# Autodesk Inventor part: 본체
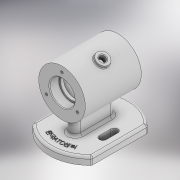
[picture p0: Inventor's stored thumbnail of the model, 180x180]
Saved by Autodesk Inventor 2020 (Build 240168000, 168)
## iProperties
Created: 2022-02
Part Number: 본체
Material: 일반
Document SubType Name: Modeling
Designer: 602-01
Density: 1 g/cm^3
Appearance: 기본값
Author: 602-01
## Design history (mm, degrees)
sketch "스케치1"
  geometry: L1 (0, 52)-(0, -52); L2 (-38, 35.496)-(-38, -35.496); L3 (38, -35.496)-(38, 35.496); A1 r 52 centre (0, 0) between (-38, -35.496) and (38, -35.496); A2 r 52 centre (0, 0) between (38, 35.496) and (-38, 35.496); 3 further points
  constraints: 6 end point, 6 point on circle, 3 coincident, 2 centre point, 2 midpoint, 1 horizontal alignment, 1 parallel, 1 vertical
  dimensions: "d1" = 76 distance between parallel lines of L2 L3; "d3" = 38 distance between parallel lines of L1 L3; "d4" = 52 radius of A1
extrude "돌출1" new body sketch "스케치1" distance "d5" = 10; taper "d6" = 0 deg
sketch "스케치2"
  geometry: 1 further point
sketch "스케치3"
  geometry: L1 (62, 36)-(62, -36); L2 (0, 35.496)-(0, -35.496) reference; L3 (62, 36)-(92, 36); L4 (62, -36)-(92, -36); L5 (92, -36)-(92, 36); L6 (78, 36)-(78, 24); L7 (78, 24)-(76, 24); L8 (76, 24)-(76, 20); L9 (76, 20)-(87, 20); L10 (87, 20)-(87, -20); L11 (87, -20)-(76, -20); L12 (76, -20)-(76, -24); L13 (76, -24)-(78, -24); L14 (78, -24)-(78, -36); 5 further points
  constraints: 26 end point, 10 perpendicular, 4 midpoint, 2 horizontal, 2 horizontal alignment, 2 point on line, 1 vertical
  dimensions: "d7" = 62 distance between parallel lines of L2 L1; "d8" = 72 distance of L1.start L1.end; "d9" = 60 diameter of L5 L1; "d10" = 32 diameter of L14 L1; "d11" = 28 diameter of L12 L1; "d12" = 50 diameter of L10 L1; "d13" = 28 diameter of L8 L1; "d14" = 32 diameter of L6 L1; "d15" = 12 distance of L6.start L6.end; "d16" = 12 distance of L13.end L14.end; "d17" = 40 distance of L9.end L10.end
revolve "회전1" sketch "스케치3" stored, may be unused: angle "d18" = 90 deg
sketch "스케치5"
  geometry: L1 (0, -19)-(0, 19); L2 (-7, -19)-(-7, 19); L3 (7, 19)-(7, -19); A1 r 7 centre (0, -19) between (-7, -19) and (7, -19); A2 r 7 centre (0, 19) between (7, 19) and (-7, 19); 1 further point
  constraints: 8 end point, 4 point on circle, 4 tangent, 2 centre point, 1 midpoint, 1 parallel, 1 vertical
  dimensions: "d21" = 14 distance between parallel lines of L3 L2; "d22" = 38 distance of L3.start L3.end
extrude "돌출2" join sketch "스케치5" stored distance "d23" = 10; taper "d24" = 0 deg
sketch "스케치6"
  geometry: L1 (-24, -7.5)-(-24, 7.5); L2 (-28.5, -7.5)-(-28.5, 7.5); L3 (-19.5, 7.5)-(-19.5, -7.5); L4 (24, -7.5)-(24, 7.5); L5 (19.5, -7.5)-(19.5, 7.5); L6 (28.5, 7.5)-(28.5, -7.5); A1 r 4.5 centre (-24, -7.5) between (-28.5, -7.5) and (-19.5, -7.5); A2 r 4.5 centre (-24, 7.5) between (-19.5, 7.5) and (-28.5, 7.5); A3 r 4.5 centre (24, -7.5) between (19.5, -7.5) and (28.5, -7.5); A4 r 4.5 centre (24, 7.5) between (28.5, 7.5) and (19.5, 7.5); 3 further points
  constraints: 16 end point, 8 point on circle, 8 tangent, 4 centre point, 3 parallel, 2 horizontal alignment, 2 midpoint, 1 vertical
  dimensions: "d25" = 24 distance from line of point (0, 0) L1; "d26" = 24 distance from line of L4 point (0, 0); "d27" = 9 distance between parallel lines of L3 L2; "d28" = 9 distance between parallel lines of L6 L5; "d29" = 15 distance of L6.start L6.end; "d30" = 15 distance of L2.start L2.end
extrude "돌출3" cut sketch "스케치6" distance "d31" = 10; taper "d32" = 0 deg
sketch "스케치7"
  geometry: C1 r 16 at (0, 0) reference; 2 further points
  constraints: 1 vertical alignment
  dimensions: "d40" = 23 distance of C1.centre point (0, 23)
hole "구멍1" sketch "스케치7" at (0, 23) diameter "d33" = 3.242; stored, may be unused: countersink angle "d37" = 90 deg, drill point angle "d39" = 120 deg; dims "d34" = 8, "d35" = 4, "d36" = 2, "d38" = 10
chamfer "모따기1" distance "d44" = 1; stored, may be unused: second distance "d45" = 2, angle "d46" = 45 deg
fillet "모깎기1" dims "d47" = 0.3
fillet "모깎기2" dims "d48" = 3
fillet "모깎기3" dims "d49" = 3
fillet "모깎기4" dims "d50" = 3
sketch "스케치12"
  geometry: L1 (-7, 13)-(-7, 30.552) reference; L2 (16.5, 90.579)-(23.428, 86.579); L3 (23.428, 86.579)-(20.428, 81.383); L4 (20.428, 81.383)-(13.5, 85.383); L5 (13.5, 85.383)-(16.5, 90.579); L6 (0, 62)-(13.5, 85.383); L7 (7, 13)-(7, 30.552) reference; 1 further point
  constraints: 10 end point, 2 perpendicular, 1 collinear, 1 parallel
  dimensions: "d88" = 30 deg angle of L7 L6; "d89" = 8 distance of L2.start L2.end; "d90" = 6 distance of L2.end L3.end; "d91" = 33 distance from line of L6.start L2
revolve "회전2" sketch "스케치12" stored, may be unused: angle "d73" = 90 deg
sketch "스케치14"
  geometry: C1 r 42.5 at (0, 0); 1 further point
  constraints: 1 centre point, 1 coincident, 1 other
  dimensions: "d85" = 85 diameter of C1
feature "엠보싱1" sketch "스케치14" dims "d1" = 76, "d3" = 38, "d4" = 52, "d86" = 0.5, "d87" = 0
sketch "스케치15"
  geometry: C1 r 8 at (0, 0) reference; 2 further points
  constraints: 1 coincident
hole "구멍4" sketch "스케치15" at (0, 0) diameter "d92" = 8; stored, may be unused: countersink angle "d96" = 90 deg, drill point angle "d98" = 0 deg; dims "d93" = 8, "d94" = 4, "d95" = 2, "d97" = 11.8
fillet "모깎기6" dims "d99" = 1
node "솔리드1"
pattern_circular "원형 패턴1" dims angle "d42" = 360 deg
mirror "미러1"
feature "A9D066F2-1C7D-4E18-AEED-F7BC21143FA4" dims "d92" = 8, "d93" = 8, "d94" = 4, "d95" = 2, "d96" = 90 deg, "d97" = 11.8, "d98" = 0
other parameters: "d0" = 52, "d68" = 30 deg
